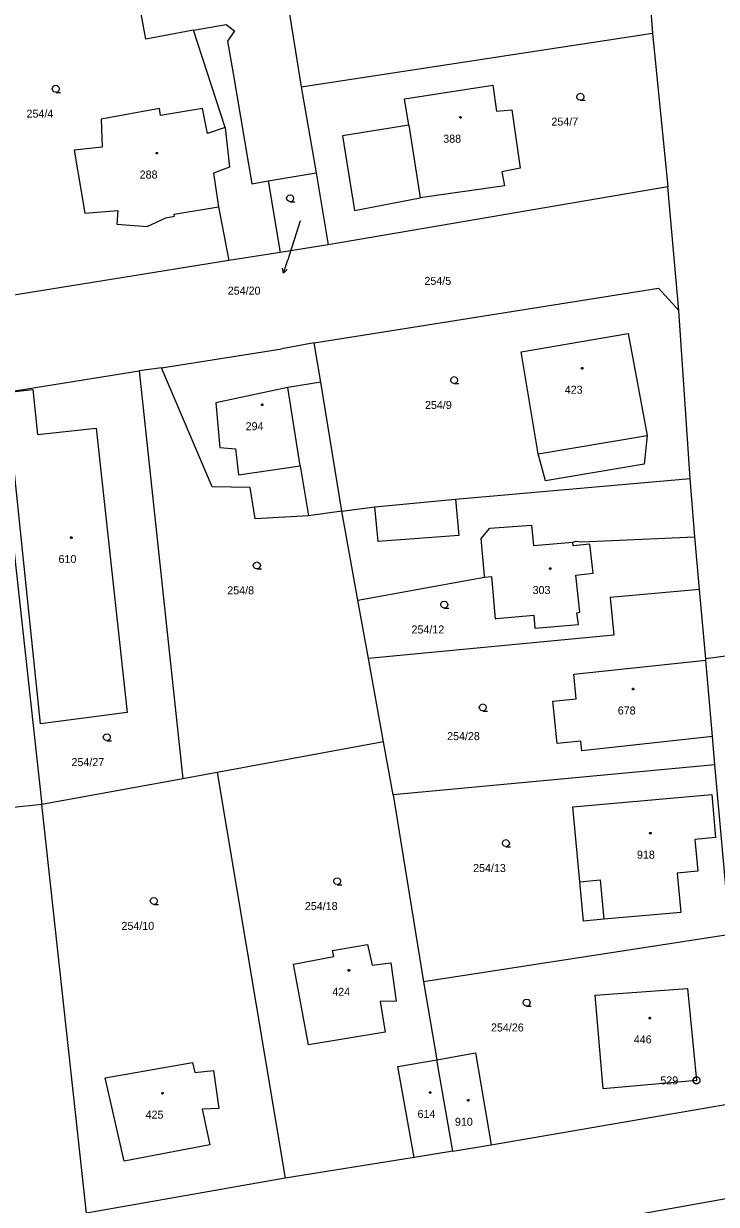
# Model space of a CAD drawing. Extents: x -757994 to -755874, y -1047691 to -1046119.
# Drawn here: x -757522.2 to -757448.7, y -1047587.6 to -1047462.2 of the extents above; entities that cross this region are included whole.
import ezdxf

# ---------------------------------------------------------------- set-up
doc = ezdxf.new("R2010")
doc.units = 0
doc.layers.add('katastrální mapa', color=7, linetype='Continuous')

msp = doc.modelspace()

# ---------------------------------------------------------------- linework, layer by layer
at = {"layer": 'katastrální mapa'}
for p, q in [((-757456.71, -1047447.3), (-757455.43, -1047463.18)), ((-757494.97, -1047455.24), (-757492.75, -1047468.9)), ((-757509.28, -1047463.82), (-757510.33, -1047458.06)), ((-757504.19, -1047462.88), (-757509.28, -1047463.82)), ((-757504.19, -1047462.88), (-757500.72, -1047462.25)), ((-757500.84, -1047473.21), (-757504.19, -1047462.88)), ((-757500.72, -1047462.25), (-757499.83, -1047462.92)), ((-757499.83, -1047462.92), (-757500.58, -1047464.04)), ((-757492.75, -1047468.9), (-757455.43, -1047463.18)), ((-757455.43, -1047463.18), (-757453.81, -1047479.5)), ((-757500.58, -1047464.04), (-757500, -1047467.45)), ((-757500, -1047467.45), (-757498, -1047479.18)), ((-757492.75, -1047468.9), (-757491.18, -1047478.02)), ((-757481.77, -1047470.14), (-757472.4, -1047468.69)), ((-757472.4, -1047468.69), (-757472, -1047471.48)), ((-757481.33, -1047472.94), (-757481.77, -1047470.14)), ((-757507.81, -1047471.2), (-757514, -1047472.3)), ((-757507.71, -1047471.93), (-757507.81, -1047471.2)), ((-757503.23, -1047471.19), (-757507.71, -1047471.93)), ((-757502.7, -1047473.85), (-757503.23, -1047471.19)), ((-757472, -1047471.48), (-757470.39, -1047471.31)), ((-757470.39, -1047471.31), (-757469.51, -1047477.52)), ((-757514, -1047472.3), (-757513.91, -1047475.28)), ((-757500.84, -1047473.21), (-757502.7, -1047473.85)), ((-757500.84, -1047473.21), (-757500.36, -1047477.43)), ((-757481.33, -1047472.94), (-757480.12, -1047480.68)), ((-757513.91, -1047475.28), (-757516.86, -1047475.62)), ((-757516.86, -1047475.62), (-757515.76, -1047482.3)), ((-757500.36, -1047477.43), (-757502.06, -1047478.04)), ((-757502.06, -1047478.04), (-757501.54, -1047481.62)), ((-757496.26, -1047478.88), (-757491.18, -1047478.02)), ((-757491.18, -1047478.02), (-757489.89, -1047485.66)), ((-757469.51, -1047477.52), (-757471.46, -1047477.9)), ((-757471.46, -1047477.9), (-757471.16, -1047479.41)), ((-757498, -1047479.18), (-757496.26, -1047478.88)), ((-757496.26, -1047478.88), (-757495, -1047486.47)), ((-757453.81, -1047479.5), (-757489.89, -1047485.66)), ((-757471.16, -1047479.41), (-757480.12, -1047480.68)), ((-757452.63, -1047492.62), (-757453.81, -1047479.5)), ((-757515.76, -1047482.3), (-757512.24, -1047482.01)), ((-757512.24, -1047482.01), (-757512.33, -1047483.45)), ((-757506.24, -1047482.42), (-757501.54, -1047481.62)), ((-757501.54, -1047481.62), (-757500.43, -1047487.34)), ((-757509.11, -1047483.72), (-757507.14, -1047482.78)), ((-757507.14, -1047482.78), (-757506.21, -1047482.62)), ((-757506.21, -1047482.62), (-757506.24, -1047482.42)), ((-757492.88, -1047483.12), (-757494.19, -1047487.24)), ((-757512.33, -1047483.45), (-757509.11, -1047483.72)), ((-757489.89, -1047485.66), (-757495, -1047486.47)), ((-757495, -1047486.47), (-757500.43, -1047487.34)), ((-757500.43, -1047487.34), (-757525.91, -1047491.41)), ((-757494.64, -1047488.67), (-757494.19, -1047487.24)), ((-757491.38, -1047496.06), (-757454.79, -1047490.26)), ((-757454.79, -1047490.26), (-757452.63, -1047492.62)), ((-757451.44, -1047510.48), (-757452.63, -1047492.62)), ((-757469.39, -1047497.03), (-757458.02, -1047495.08)), ((-757458.02, -1047495.08), (-757456, -1047505.9)), ((-757507.6, -1047498.71), (-757494.8, -1047496.71)), ((-757491.38, -1047496.06), (-757494.8, -1047496.71)), ((-757490.69, -1047500.25), (-757491.38, -1047496.06)), ((-757467.57, -1047507.87), (-757469.39, -1047497.03)), ((-757524.99, -1047501.43), (-757509.96, -1047499.03)), ((-757507.6, -1047498.71), (-757509.96, -1047499.03)), ((-757509.96, -1047499.03), (-757505.34, -1047542.35)), ((-757502.23, -1047511.34), (-757507.6, -1047498.71)), ((-757494.17, -1047500.8), (-757501.83, -1047502.42)), ((-757490.69, -1047500.25), (-757494.17, -1047500.8)), ((-757492.86, -1047509.12), (-757494.17, -1047500.8)), ((-757488.43, -1047513.94), (-757490.69, -1047500.25)), ((-757524.11, -1047501.34), (-757521.27, -1047501.02)), ((-757520.47, -1047536.52), (-757524.11, -1047501.34)), ((-757521.27, -1047501.02), (-757520.78, -1047505.79)), ((-757501.83, -1047502.42), (-757501.41, -1047507.19)), ((-757520.78, -1047505.79), (-757514.55, -1047505.14)), ((-757514.55, -1047505.14), (-757511.23, -1047535.31)), ((-757467.57, -1047507.87), (-757456, -1047505.9)), ((-757456, -1047505.9), (-757456.34, -1047508.96)), ((-757501.41, -1047507.19), (-757499.74, -1047507.31)), ((-757524.45, -1047507.31), (-757520.32, -1047545.09)), ((-757499.74, -1047507.31), (-757499.42, -1047510.1)), ((-757466.82, -1047510.73), (-757467.57, -1047507.87)), ((-757499.42, -1047510.1), (-757492.86, -1047509.12)), ((-757492.86, -1047509.12), (-757491.99, -1047514.44)), ((-757456.34, -1047508.96), (-757466.82, -1047510.73)), ((-757476.38, -1047512.65), (-757451.44, -1047510.48)), ((-757450.96, -1047516.65), (-757451.44, -1047510.48)), ((-757498.19, -1047511.43), (-757502.23, -1047511.34)), ((-757497.64, -1047514.76), (-757498.19, -1047511.43)), ((-757488.43, -1047513.94), (-757484.95, -1047513.47)), ((-757484.95, -1047513.47), (-757476.38, -1047512.65)), ((-757484.57, -1047517.15), (-757484.95, -1047513.47)), ((-757476.38, -1047512.65), (-757476.02, -1047516.52)), ((-757491.99, -1047514.44), (-757497.64, -1047514.76)), ((-757488.43, -1047513.94), (-757491.99, -1047514.44)), ((-757486.73, -1047523.39), (-757488.43, -1047513.94)), ((-757473.63, -1047516.86), (-757472.71, -1047515.76)), ((-757472.71, -1047515.76), (-757468.29, -1047515.42)), ((-757468.29, -1047515.42), (-757468.09, -1047517.6)), ((-757476.02, -1047516.52), (-757484.57, -1047517.15)), ((-757473.29, -1047520.82), (-757473.63, -1047516.86)), ((-757468.09, -1047517.6), (-757463.9, -1047517.22)), ((-757463.9, -1047517.22), (-757463.55, -1047517.11)), ((-757463.87, -1047517.61), (-757463.9, -1047517.22)), ((-757463.55, -1047517.11), (-757462.96, -1047517.18)), ((-757462.96, -1047517.18), (-757450.96, -1047516.65)), ((-757450.45, -1047522.25), (-757450.96, -1047516.65)), ((-757462.1, -1047517.45), (-757463.87, -1047517.61)), ((-757461.76, -1047520.54), (-757462.1, -1047517.45)), ((-757486.73, -1047523.39), (-757473.28, -1047520.94)), ((-757473.28, -1047520.94), (-757473.29, -1047520.82)), ((-757473.28, -1047520.94), (-757472.53, -1047520.88)), ((-757472.53, -1047520.88), (-757472.15, -1047525.36)), ((-757463.59, -1047520.74), (-757461.76, -1047520.54)), ((-757463.17, -1047524.68), (-757463.59, -1047520.74)), ((-757450.45, -1047522.25), (-757459.95, -1047523.1)), ((-757449.79, -1047529.61), (-757450.45, -1047522.25)), ((-757485.61, -1047529.59), (-757486.73, -1047523.39)), ((-757459.95, -1047523.1), (-757459.56, -1047527.09)), ((-757463.47, -1047524.72), (-757463.17, -1047524.68)), ((-757463.32, -1047525.99), (-757463.47, -1047524.72)), ((-757472.15, -1047525.36), (-757472.03, -1047525.35)), ((-757472.03, -1047525.35), (-757468.04, -1047525)), ((-757468.04, -1047525), (-757467.93, -1047526.38)), ((-757467.93, -1047526.38), (-757463.32, -1047525.99)), ((-757459.56, -1047527.09), (-757485.61, -1047529.59)), ((-757484.02, -1047538.45), (-757485.61, -1047529.59)), ((-757463.81, -1047531.26), (-757449.78, -1047529.75)), ((-757443.57, -1047528.78), (-757449.79, -1047529.61)), ((-757449.78, -1047529.75), (-757449.79, -1047529.61)), ((-757449.08, -1047537.87), (-757449.78, -1047529.75)), ((-757463.54, -1047533.86), (-757463.81, -1047531.26)), ((-757466.04, -1047534.13), (-757463.54, -1047533.86)), ((-757465.57, -1047538.61), (-757466.04, -1047534.13)), ((-757511.23, -1047535.31), (-757520.47, -1047536.52)), ((-757484.02, -1047538.45), (-757501.67, -1047541.68)), ((-757482.99, -1047544.06), (-757484.02, -1047538.45)), ((-757463.07, -1047538.35), (-757465.57, -1047538.61)), ((-757462.96, -1047539.38), (-757463.07, -1047538.35)), ((-757449.08, -1047537.87), (-757462.96, -1047539.38)), ((-757448.82, -1047540.88), (-757449.08, -1047537.87)), ((-757448.82, -1047540.88), (-757482.99, -1047544.06)), ((-757447.2, -1047558.89), (-757448.82, -1047540.88)), ((-757505.34, -1047542.35), (-757520.32, -1047545.09)), ((-757501.67, -1047541.68), (-757505.34, -1047542.35)), ((-757501.67, -1047541.68), (-757494.47, -1047584.75)), ((-757482.99, -1047544.06), (-757479.77, -1047563.91)), ((-757463.91, -1047545.33), (-757449.15, -1047544.02)), ((-757449.15, -1047544.02), (-757448.74, -1047548.6)), ((-757520.32, -1047545.09), (-757545.19, -1047547.67)), ((-757515.55, -1047588.48), (-757520.32, -1047545.09)), ((-757463.16, -1047553.3), (-757463.91, -1047545.33)), ((-757448.74, -1047548.6), (-757450.93, -1047548.79)), ((-757450.93, -1047548.79), (-757450.63, -1047552.16)), ((-757450.63, -1047552.16), (-757452.82, -1047552.37)), ((-757452.82, -1047552.37), (-757452.44, -1047556.54)), ((-757463.16, -1047553.3), (-757460.99, -1047553.1)), ((-757462.76, -1047557.47), (-757463.16, -1047553.3)), ((-757460.99, -1047553.1), (-757460.62, -1047557.28)), ((-757460.62, -1047557.28), (-757462.76, -1047557.47)), ((-757452.44, -1047556.54), (-757460.62, -1047557.28)), ((-757447.2, -1047558.89), (-757479.77, -1047563.91)), ((-757489.45, -1047560.6), (-757485.73, -1047559.95)), ((-757489.3, -1047561.24), (-757489.45, -1047560.6)), ((-757485.73, -1047559.95), (-757485.21, -1047562.15)), ((-757493.58, -1047562.03), (-757489.3, -1047561.24)), ((-757492, -1047570.6), (-757493.58, -1047562.03)), ((-757485.21, -1047562.15), (-757483.23, -1047561.89)), ((-757483.23, -1047561.89), (-757482.68, -1047565.98)), ((-757479.77, -1047563.91), (-757478.34, -1047572.2)), ((-757461.54, -1047565.35), (-757451.74, -1047564.61)), ((-757451.74, -1047564.61), (-757450.76, -1047574.38)), ((-757482.68, -1047565.98), (-757484.37, -1047566.02)), ((-757484.37, -1047566.02), (-757483.84, -1047569.28)), ((-757460.7, -1047575.28), (-757461.54, -1047565.35)), ((-757483.84, -1047569.28), (-757492, -1047570.6)), ((-757482.5, -1047572.92), (-757478.34, -1047572.2)), ((-757478.34, -1047572.2), (-757474.24, -1047571.45)), ((-757476.66, -1047581.91), (-757478.34, -1047572.2)), ((-757474.24, -1047571.45), (-757472.57, -1047581.21)), ((-757513.6, -1047574.1), (-757504.29, -1047572.48)), ((-757504.29, -1047572.48), (-757504.05, -1047573.54)), ((-757504.05, -1047573.54), (-757502.07, -1047573.32)), ((-757502.07, -1047573.32), (-757501.52, -1047577.37)), ((-757480.77, -1047582.57), (-757482.5, -1047572.92)), ((-757511.58, -1047582.95), (-757513.6, -1047574.1)), ((-757450.76, -1047574.38), (-757460.7, -1047575.28)), ((-757450.79, -1047574.38), (-757450.73, -1047574.38)), ((-757501.52, -1047577.37), (-757503.28, -1047577.45)), ((-757503.28, -1047577.45), (-757502.48, -1047581.24)), ((-757472.57, -1047581.21), (-757445.67, -1047576.6)), ((-757502.48, -1047581.24), (-757511.58, -1047582.95)), ((-757476.66, -1047581.91), (-757472.57, -1047581.21)), ((-757476.66, -1047581.91), (-757480.77, -1047582.57)), ((-757480.77, -1047582.57), (-757494.47, -1047584.75)), ((-757494.47, -1047584.75), (-757515.55, -1047588.48)), ((-757445.8, -1047586.62), (-757473.85, -1047591.63))]:
    msp.add_line(p, q, dxfattribs=at)
for points in [[(-757518.83, -1047469.46), (-757519.02, -1047469.41), (-757519.16, -1047469.27), (-757519.21, -1047469.09), (-757519.16, -1047468.91), (-757519.02, -1047468.77), (-757518.84, -1047468.72), (-757518.65, -1047468.77), (-757518.51, -1047468.91), (-757518.47, -1047469.1), (-757518.51, -1047469.28), (-757518.65, -1047469.42), (-757518.84, -1047469.47), (-757518.34, -1047469.47)], [(-757463.1, -1047470.3), (-757463.29, -1047470.25), (-757463.43, -1047470.12), (-757463.48, -1047469.93), (-757463.43, -1047469.75), (-757463.29, -1047469.61), (-757463.1, -1047469.56), (-757462.92, -1047469.61), (-757462.78, -1047469.75), (-757462.73, -1047469.94), (-757462.78, -1047470.12), (-757462.92, -1047470.26), (-757463.11, -1047470.31), (-757462.61, -1047470.31)], [(-757481.33, -1047472.94), (-757488.36, -1047474.08), (-757487.11, -1047482.01), (-757480.12, -1047480.68)], [(-757493.93, -1047481.09), (-757494.12, -1047481.04), (-757494.26, -1047480.91), (-757494.31, -1047480.72), (-757494.26, -1047480.53), (-757494.12, -1047480.4), (-757493.94, -1047480.35), (-757493.75, -1047480.4), (-757493.61, -1047480.53), (-757493.57, -1047480.73), (-757493.61, -1047480.92), (-757493.75, -1047481.05), (-757493.94, -1047481.1), (-757493.44, -1047481.1)], [(-757494.25, -1047488.27), (-757494.64, -1047488.67), (-757494.73, -1047488.12)], [(-757476.5, -1047500.39), (-757476.69, -1047500.34), (-757476.83, -1047500.21), (-757476.88, -1047500.02), (-757476.83, -1047499.84), (-757476.69, -1047499.7), (-757476.51, -1047499.65), (-757476.32, -1047499.7), (-757476.19, -1047499.84), (-757476.14, -1047500.03), (-757476.19, -1047500.22), (-757476.32, -1047500.35), (-757476.51, -1047500.4), (-757476.01, -1047500.4)], [(-757497.47, -1047520.07), (-757497.66, -1047520.02), (-757497.79, -1047519.89), (-757497.85, -1047519.7), (-757497.79, -1047519.51), (-757497.66, -1047519.38), (-757497.48, -1047519.33), (-757497.29, -1047519.38), (-757497.16, -1047519.51), (-757497.1, -1047519.71), (-757497.16, -1047519.9), (-757497.29, -1047520.03), (-757497.48, -1047520.08), (-757496.98, -1047520.08)], [(-757477.56, -1047524.23), (-757477.75, -1047524.18), (-757477.89, -1047524.04), (-757477.94, -1047523.86), (-757477.89, -1047523.68), (-757477.75, -1047523.54), (-757477.57, -1047523.49), (-757477.38, -1047523.54), (-757477.25, -1047523.68), (-757477.2, -1047523.87), (-757477.25, -1047524.05), (-757477.38, -1047524.19), (-757477.57, -1047524.24), (-757477.07, -1047524.24)], [(-757473.46, -1047535.15), (-757473.65, -1047535.1), (-757473.78, -1047534.97), (-757473.84, -1047534.78), (-757473.78, -1047534.6), (-757473.65, -1047534.46), (-757473.47, -1047534.41), (-757473.28, -1047534.46), (-757473.15, -1047534.6), (-757473.1, -1047534.79), (-757473.15, -1047534.98), (-757473.28, -1047535.11), (-757473.47, -1047535.16), (-757472.97, -1047535.16)], [(-757513.41, -1047538.31), (-757513.6, -1047538.26), (-757513.74, -1047538.12), (-757513.79, -1047537.94), (-757513.74, -1047537.76), (-757513.6, -1047537.62), (-757513.42, -1047537.57), (-757513.23, -1047537.62), (-757513.1, -1047537.76), (-757513.05, -1047537.95), (-757513.1, -1047538.14), (-757513.23, -1047538.27), (-757513.42, -1047538.32), (-757512.92, -1047538.32)], [(-757471.01, -1047549.56), (-757471.2, -1047549.51), (-757471.34, -1047549.38), (-757471.39, -1047549.19), (-757471.34, -1047549.01), (-757471.2, -1047548.87), (-757471.02, -1047548.82), (-757470.83, -1047548.87), (-757470.7, -1047549.01), (-757470.65, -1047549.2), (-757470.7, -1047549.39), (-757470.83, -1047549.52), (-757471.02, -1047549.57), (-757470.52, -1047549.57)], [(-757488.93, -1047553.6), (-757489.12, -1047553.55), (-757489.26, -1047553.42), (-757489.31, -1047553.23), (-757489.26, -1047553.04), (-757489.12, -1047552.91), (-757488.94, -1047552.86), (-757488.75, -1047552.91), (-757488.61, -1047553.04), (-757488.57, -1047553.24), (-757488.61, -1047553.43), (-757488.75, -1047553.56), (-757488.94, -1047553.61), (-757488.44, -1047553.61)], [(-757508.41, -1047555.7), (-757508.6, -1047555.65), (-757508.74, -1047555.51), (-757508.79, -1047555.33), (-757508.74, -1047555.15), (-757508.6, -1047555.01), (-757508.42, -1047554.96), (-757508.23, -1047555.01), (-757508.1, -1047555.15), (-757508.05, -1047555.34), (-757508.1, -1047555.52), (-757508.23, -1047555.66), (-757508.42, -1047555.71), (-757507.92, -1047555.71)], [(-757468.81, -1047566.49), (-757469, -1047566.44), (-757469.14, -1047566.3), (-757469.19, -1047566.12), (-757469.14, -1047565.94), (-757469, -1047565.8), (-757468.82, -1047565.75), (-757468.63, -1047565.8), (-757468.5, -1047565.94), (-757468.45, -1047566.12), (-757468.5, -1047566.32), (-757468.63, -1047566.45), (-757468.82, -1047566.5), (-757468.32, -1047566.5)]]:
    msp.add_lwpolyline(points, dxfattribs=at)
for points in [[(-757475.84, -1047472.03), (-757475.79, -1047472.04), (-757475.76, -1047472.09), (-757475.75, -1047472.12), (-757475.76, -1047472.17), (-757475.8, -1047472.2), (-757475.84, -1047472.21), (-757475.89, -1047472.19), (-757475.92, -1047472.16), (-757475.93, -1047472.12), (-757475.92, -1047472.08), (-757475.88, -1047472.04)], [(-757508.1, -1047475.84), (-757508.05, -1047475.85), (-757508.02, -1047475.89), (-757508.01, -1047475.92), (-757508.02, -1047475.97), (-757508.07, -1047476), (-757508.1, -1047476.01), (-757508.15, -1047475.99), (-757508.18, -1047475.96), (-757508.19, -1047475.92), (-757508.18, -1047475.88), (-757508.14, -1047475.84)], [(-757462.91, -1047498.69), (-757462.86, -1047498.7), (-757462.84, -1047498.74), (-757462.83, -1047498.77), (-757462.84, -1047498.82), (-757462.88, -1047498.85), (-757462.91, -1047498.86), (-757462.96, -1047498.84), (-757462.99, -1047498.81), (-757463, -1047498.77), (-757462.99, -1047498.73), (-757462.95, -1047498.69)], [(-757496.89, -1047502.55), (-757496.84, -1047502.57), (-757496.82, -1047502.61), (-757496.8, -1047502.64), (-757496.82, -1047502.69), (-757496.85, -1047502.72), (-757496.89, -1047502.73), (-757496.94, -1047502.71), (-757496.97, -1047502.68), (-757496.98, -1047502.64), (-757496.97, -1047502.6), (-757496.93, -1047502.56)], [(-757517.18, -1047516.67), (-757517.13, -1047516.68), (-757517.1, -1047516.72), (-757517.1, -1047516.75), (-757517.1, -1047516.79), (-757517.15, -1047516.83), (-757517.18, -1047516.84), (-757517.23, -1047516.82), (-757517.26, -1047516.79), (-757517.27, -1047516.75), (-757517.26, -1047516.71), (-757517.22, -1047516.67)], [(-757466.3, -1047519.96), (-757466.25, -1047519.97), (-757466.23, -1047520.01), (-757466.22, -1047520.04), (-757466.23, -1047520.09), (-757466.27, -1047520.12), (-757466.3, -1047520.12), (-757466.35, -1047520.11), (-757466.38, -1047520.08), (-757466.39, -1047520.04), (-757466.38, -1047520), (-757466.34, -1047519.96)], [(-757457.5, -1047532.74), (-757457.45, -1047532.75), (-757457.43, -1047532.8), (-757457.42, -1047532.83), (-757457.43, -1047532.88), (-757457.47, -1047532.91), (-757457.5, -1047532.92), (-757457.54, -1047532.9), (-757457.58, -1047532.87), (-757457.59, -1047532.83), (-757457.58, -1047532.78), (-757457.53, -1047532.75)], [(-757455.67, -1047548.05), (-757455.62, -1047548.07), (-757455.6, -1047548.11), (-757455.59, -1047548.14), (-757455.6, -1047548.19), (-757455.64, -1047548.22), (-757455.67, -1047548.23), (-757455.72, -1047548.21), (-757455.75, -1047548.18), (-757455.76, -1047548.14), (-757455.75, -1047548.1), (-757455.71, -1047548.06)], [(-757487.69, -1047562.62), (-757487.64, -1047562.62), (-757487.61, -1047562.67), (-757487.6, -1047562.7), (-757487.61, -1047562.74), (-757487.66, -1047562.78), (-757487.69, -1047562.78), (-757487.73, -1047562.77), (-757487.76, -1047562.74), (-757487.77, -1047562.7), (-757487.76, -1047562.66), (-757487.72, -1047562.62)], [(-757455.73, -1047567.68), (-757455.68, -1047567.69), (-757455.66, -1047567.73), (-757455.65, -1047567.76), (-757455.66, -1047567.8), (-757455.7, -1047567.84), (-757455.73, -1047567.85), (-757455.77, -1047567.83), (-757455.8, -1047567.8), (-757455.82, -1047567.76), (-757455.8, -1047567.72), (-757455.76, -1047567.68)], [(-757450.67, -1047574.02), (-757450.49, -1047574.12), (-757450.4, -1047574.29), (-757450.4, -1047574.48), (-757450.49, -1047574.65), (-757450.67, -1047574.74), (-757450.86, -1047574.74), (-757451.03, -1047574.65), (-757451.12, -1047574.48), (-757451.12, -1047574.29), (-757451.03, -1047574.12), (-757450.86, -1047574.02)], [(-757507.48, -1047575.67), (-757507.43, -1047575.68), (-757507.41, -1047575.72), (-757507.4, -1047575.75), (-757507.41, -1047575.79), (-757507.45, -1047575.83), (-757507.48, -1047575.84), (-757507.52, -1047575.82), (-757507.55, -1047575.79), (-757507.57, -1047575.75), (-757507.55, -1047575.71), (-757507.51, -1047575.67)], [(-757479.06, -1047575.59), (-757479.01, -1047575.6), (-757478.99, -1047575.64), (-757478.98, -1047575.67), (-757478.99, -1047575.72), (-757479.03, -1047575.75), (-757479.06, -1047575.76), (-757479.1, -1047575.74), (-757479.14, -1047575.71), (-757479.15, -1047575.67), (-757479.14, -1047575.62), (-757479.1, -1047575.59)], [(-757475.01, -1047576.42), (-757474.96, -1047576.43), (-757474.94, -1047576.47), (-757474.93, -1047576.5), (-757474.94, -1047576.54), (-757474.98, -1047576.58), (-757475.01, -1047576.59), (-757475.05, -1047576.57), (-757475.09, -1047576.54), (-757475.1, -1047576.5), (-757475.09, -1047576.46), (-757475.04, -1047576.42)]]:
    msp.add_lwpolyline(points, close=True, dxfattribs=at)

# ---------------------------------------------------------------- texts
for s, height, p in [('254/4', 0.85, (-757521.94, -1047472.16)), ('254/7', 0.85, (-757466.18, -1047473)), ('388', 0.85, (-757477.67, -1047474.82)), ('288', 0.85, (-757509.92, -1047478.62)), ('254/20', 0.05, (-757492.87, -1047483.12)), ('254/5', 0.85, (-757479.67, -1047489.91)), ('254/20', 0.85, (-757500.56, -1047490.95)), ('423', 0.85, (-757464.76, -1047501.47)), ('254/9', 0.85, (-757479.61, -1047503.09)), ('294', 0.85, (-757498.66, -1047505.34)), ('610', 0.85, (-757518.54, -1047519.45)), ('254/8', 0.85, (-757500.61, -1047522.77)), ('303', 0.85, (-757468.18, -1047522.74)), ('254/12', 0.85, (-757481.04, -1047526.93)), ('678', 0.85, (-757459.13, -1047535.53)), ('254/28', 0.85, (-757477.26, -1047538.25)), ('254/27', 0.85, (-757517.16, -1047541.01)), ('918', 0.85, (-757457.09, -1047550.84)), ('254/13', 0.85, (-757474.5, -1047552.26)), ('254/18', 0.85, (-757492.37, -1047556.3)), ('254/10', 0.85, (-757511.85, -1047558.4)), ('424', 0.85, (-757489.46, -1047565.4)), ('254/26', 0.85, (-757472.6, -1047569.19)), ('446', 0.85, (-757457.43, -1047570.46)), ('529', 0.85, (-757454.61, -1047574.81)), ('425', 0.85, (-757509.29, -1047578.45)), ('614', 0.85, (-757480.4, -1047578.37)), ('910', 0.85, (-757476.43, -1047579.2))]:
    msp.add_text(s, height=height, dxfattribs=at).set_placement(p)

doc.saveas('drawing.dxf')
